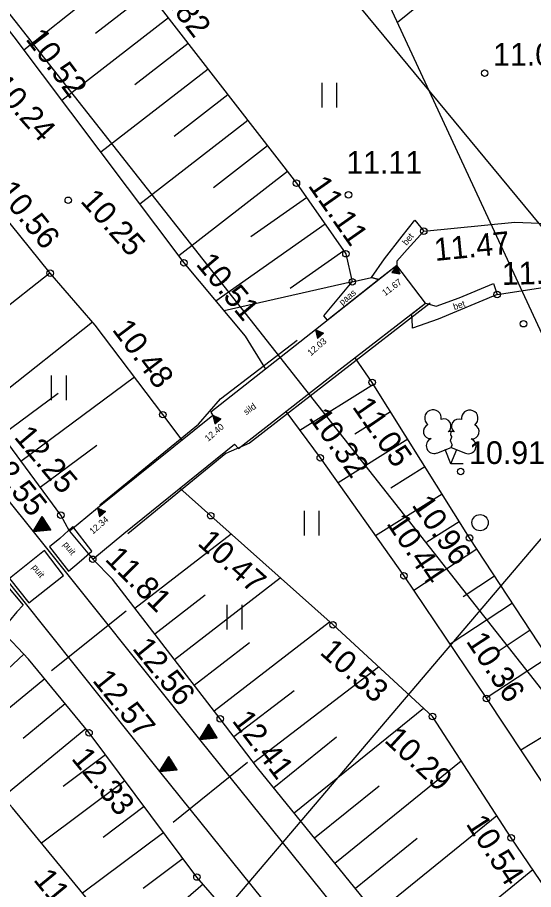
# Model space of a CAD drawing. Extents: x 554198 to 554371, y 6593448 to 6593563.
# Drawn here: x 554296.62 to 554312.55, y 6593507.8 to 6593534.71 of the extents above; entities that cross this region are included whole.
import ezdxf

# ---------------------------------------------------------------- set-up
doc = ezdxf.new("R2010")
doc.units = 0
for name, color, linetype in [('AED', 7, 'Continuous'), ('HALJASTUS', 7, 'Continuous'), ('KORGUS-EH2000', 7, 'Continuous'), ('PIIR', 7, 'Continuous'), ('POST', 7, 'Continuous'), ('PUU', 7, 'Continuous'), ('RAJATIS', 7, 'Continuous'), ('RAJATISEDET', 7, 'Continuous'), ('RDT', 7, 'Continuous'), ('RELJEEF', 7, 'Continuous'), ('SIOHULIIN', 7, 'Continuous'), ('TEE', 7, 'Continuous'), ('VTRASS', 7, 'Continuous')]:
    doc.layers.add(name, color=color, linetype=linetype)

msp = doc.modelspace()

# ---------------------------------------------------------------- linework, layer by layer
at = {"layer": 'AED'}
for points in [[(554309.359, 6593525.893), (554303.78, 6593521.577), (554303.057, 6593521.253), (554300.026, 6593518.783)], [(554299.165, 6593519.676), (554302.21, 6593522.165), (554302.89, 6593522.94), (554305.253, 6593524.758), (554305.253, 6593524.758)]]:
    msp.add_lwpolyline(points, dxfattribs=at)
at = {"layer": 'HALJASTUS'}
for p, q in [((554306.014, 6593532.693), (554306.014, 6593531.932)), ((554306.469, 6593532.693), (554306.469, 6593531.932)), ((554297.665, 6593523.668), (554297.665, 6593522.907)), ((554298.121, 6593523.668), (554298.121, 6593522.907)), ((554305.471, 6593519.49), (554305.471, 6593518.729)), ((554305.927, 6593519.49), (554305.927, 6593518.729)), ((554303.088, 6593516.59), (554303.088, 6593515.829)), ((554303.543, 6593516.59), (554303.543, 6593515.829))]:
    msp.add_line(p, q, dxfattribs=at)
at = {"layer": 'KORGUS-EH2000'}
for p, q in [((554297.103, 6593518.851), (554297.388, 6593519.316)), ((554297.349, 6593519.252), (554297.311, 6593518.868)), ((554297.379, 6593519.3), (554297.336, 6593518.871)), ((554297.403, 6593519.293), (554297.361, 6593518.873)), ((554297.425, 6593519.257), (554297.387, 6593518.875)), ((554297.647, 6593518.897), (554297.388, 6593519.316)), ((554297.199, 6593519.007), (554297.184, 6593518.858)), ((554297.229, 6593519.056), (554297.209, 6593518.86)), ((554297.259, 6593519.105), (554297.235, 6593518.862)), ((554297.289, 6593519.154), (554297.26, 6593518.864)), ((554297.319, 6593519.203), (554297.285, 6593518.866)), ((554297.446, 6593519.222), (554297.412, 6593518.877)), ((554297.468, 6593519.187), (554297.437, 6593518.879)), ((554297.489, 6593519.152), (554297.463, 6593518.881)), ((554297.511, 6593519.117), (554297.488, 6593518.883)), ((554297.533, 6593519.082), (554297.513, 6593518.885)), ((554297.554, 6593519.047), (554297.539, 6593518.888)), ((554297.576, 6593519.012), (554297.564, 6593518.89)), ((554297.103, 6593518.851), (554297.647, 6593518.897)), ((554297.109, 6593518.861), (554297.108, 6593518.851)), ((554297.139, 6593518.909), (554297.133, 6593518.854)), ((554297.169, 6593518.958), (554297.159, 6593518.856)), ((554297.598, 6593518.976), (554297.589, 6593518.892)), ((554297.619, 6593518.941), (554297.615, 6593518.894)), ((554297.641, 6593518.906), (554297.64, 6593518.896)), ((554302.239, 6593512.436), (554302.524, 6593512.901)), ((554302.485, 6593512.837), (554302.447, 6593512.453)), ((554302.515, 6593512.885), (554302.472, 6593512.456)), ((554302.539, 6593512.878), (554302.497, 6593512.458)), ((554302.561, 6593512.842), (554302.523, 6593512.46)), ((554302.783, 6593512.482), (554302.524, 6593512.901)), ((554302.582, 6593512.807), (554302.548, 6593512.462)), ((554302.305, 6593512.543), (554302.295, 6593512.441)), ((554302.335, 6593512.592), (554302.32, 6593512.443)), ((554302.365, 6593512.641), (554302.345, 6593512.445)), ((554302.395, 6593512.69), (554302.371, 6593512.447)), ((554302.425, 6593512.739), (554302.396, 6593512.449)), ((554302.455, 6593512.788), (554302.421, 6593512.451)), ((554302.604, 6593512.772), (554302.573, 6593512.464)), ((554302.625, 6593512.737), (554302.599, 6593512.466)), ((554302.647, 6593512.702), (554302.624, 6593512.468)), ((554302.669, 6593512.667), (554302.649, 6593512.47)), ((554302.69, 6593512.632), (554302.675, 6593512.473)), ((554302.712, 6593512.597), (554302.7, 6593512.475)), ((554302.734, 6593512.561), (554302.725, 6593512.477)), ((554302.755, 6593512.526), (554302.751, 6593512.479)), ((554302.239, 6593512.436), (554302.783, 6593512.482)), ((554302.245, 6593512.446), (554302.244, 6593512.436)), ((554302.275, 6593512.494), (554302.269, 6593512.439)), ((554302.777, 6593512.491), (554302.776, 6593512.481)), ((554301.007, 6593511.447), (554301.292, 6593511.912)), ((554301.193, 6593511.75), (554301.164, 6593511.46)), ((554301.223, 6593511.799), (554301.189, 6593511.462)), ((554301.253, 6593511.848), (554301.215, 6593511.464)), ((554301.283, 6593511.896), (554301.24, 6593511.467)), ((554301.307, 6593511.889), (554301.265, 6593511.469)), ((554301.329, 6593511.853), (554301.291, 6593511.471)), ((554301.551, 6593511.493), (554301.292, 6593511.912)), ((554301.35, 6593511.818), (554301.316, 6593511.473)), ((554301.372, 6593511.783), (554301.341, 6593511.475)), ((554301.393, 6593511.748), (554301.367, 6593511.477)), ((554301.415, 6593511.713), (554301.392, 6593511.479)), ((554301.007, 6593511.447), (554301.551, 6593511.493)), ((554301.013, 6593511.457), (554301.012, 6593511.447)), ((554301.043, 6593511.505), (554301.037, 6593511.45)), ((554301.073, 6593511.554), (554301.063, 6593511.452)), ((554301.103, 6593511.603), (554301.088, 6593511.454)), ((554301.133, 6593511.652), (554301.113, 6593511.456)), ((554301.163, 6593511.701), (554301.139, 6593511.458)), ((554301.437, 6593511.678), (554301.417, 6593511.481)), ((554301.458, 6593511.643), (554301.443, 6593511.484)), ((554301.48, 6593511.608), (554301.468, 6593511.486)), ((554301.502, 6593511.572), (554301.493, 6593511.488)), ((554301.523, 6593511.537), (554301.519, 6593511.49)), ((554301.545, 6593511.502), (554301.544, 6593511.492))]:
    msp.add_line(p, q, dxfattribs=at)
for centre in [(554311.04, 6593532.99), (554305.23, 6593529.6), (554306.84, 6593529.24), (554298.19, 6593529.07), (554309.16, 6593528.115), (554306.759, 6593527.42), (554301.76, 6593527.14), (554297.63, 6593526.82), (554306.956, 6593526.554), (554311.427, 6593526.164), (554312.24, 6593525.26), (554307.568, 6593523.452), (554301.107, 6593522.455), (554305.968, 6593521.122), (554310.3, 6593520.7), (554297.959, 6593519.355), (554302.586, 6593519.337), (554310.57, 6593518.65), (554298.943, 6593517.994), (554308.55, 6593517.48), (554306.36, 6593515.97), (554311.096, 6593513.696), (554302.88, 6593513.07), (554309.432, 6593513.141), (554298.83, 6593512.64), (554311.86, 6593509.4), (554302.161, 6593508.188)]:
    msp.add_circle(centre, 0.1, dxfattribs=at)
at = {"layer": 'PIIR'}
for p, q in [((554289.426, 6593543.649), (554309.59, 6593518.04)), ((554309.59, 6593518.04), (554321.626, 6593502.754))]:
    msp.add_line(p, q, dxfattribs=at)
at = {"layer": 'POST'}
msp.add_circle((554310.899, 6593519.124), 0.25, dxfattribs=at)
at = {"layer": 'PUU'}
for p, q in [((554309.561, 6593521.271), (554310.006, 6593521.446)), ((554310.006, 6593521.446), (554310.446, 6593521.266)), ((554310.001, 6593520.936), (554309.826, 6593521.376)), ((554310.001, 6593520.936), (554310.181, 6593521.376)), ((554310.381, 6593520.936), (554310.001, 6593520.936))]:
    msp.add_line(p, q, dxfattribs=at)
msp.add_lwpolyline([(554310.006, 6593521.941), (554309.986, 6593521.866), (554309.986, 6593521.846), (554309.996, 6593521.816), (554310.016, 6593521.781), (554310.021, 6593521.761), (554310.006, 6593521.726), (554309.981, 6593521.676), (554309.976, 6593521.651), (554309.981, 6593521.636), (554309.991, 6593521.606), (554310.026, 6593521.546), (554310.031, 6593521.526), (554310.026, 6593521.506), (554310.011, 6593521.471), (554310.006, 6593521.446)], dxfattribs=at)
for centre, radius, start, end in [((554309.444, 6593522.35), 0.256, 111.5027, 232.5173), ((554309.444, 6593522.35), 0.256, 350.4856, 111.5002), ((554310.58, 6593522.341), 0.256, 67.6168, 188.6314), ((554310.58, 6593522.341), 0.256, 306.5997, 67.6143), ((554309.779, 6593522.1), 0.224, 308.5041, 111.5725), ((554310.242, 6593522.095), 0.225, 67.7016, 230.5126), ((554309.37, 6593521.939), 0.224, 111.4304, 274.4987), ((554310.005, 6593521.703), 0.237, 66.7655, 111.5015), ((554310.647, 6593521.929), 0.224, 264.6183, 67.6866), ((554309.475, 6593521.494), 0.237, 111.5014, 291.5004), ((554310.536, 6593521.486), 0.237, 247.6166, 67.6155)]:
    msp.add_arc(centre, radius, start, end, dxfattribs=at)
at = {"layer": 'RAJATIS'}
for points in [[(554303.446, 6593521.406), (554306.637, 6593523.901), (554309.218, 6593525.899), (554308.331, 6593527.062), (554305.816, 6593525.073), (554302.594, 6593522.531), (554302.648, 6593522.432), (554299.091, 6593519.572), (554298.491, 6593519.075), (554298.228, 6593518.857), (554298.943, 6593517.994), (554299.902, 6593518.791), (554303.315, 6593521.546)], [(554296.378, 6593517.399), (554296.971, 6593516.654), (554298.04, 6593517.497), (554297.458, 6593518.268)], [(554295.41, 6593516.667), (554295.987, 6593517.134), (554296.216, 6593517.272), (554296.795, 6593516.578), (554296.603, 6593516.372), (554296.134, 6593515.797)]]:
    msp.add_lwpolyline(points, close=True, dxfattribs=at)
msp.add_lwpolyline([(554297.61, 6593518.38), (554298.199, 6593517.628), (554298.529, 6593517.903), (554298.914, 6593518.24), (554298.331, 6593519.007), (554297.925, 6593518.636), (554297.61, 6593518.38)], dxfattribs=at)
at = {"layer": 'RAJATISEDET'}
for p, q in [((554308.331, 6593527.062), (554308.175, 6593526.838)), ((554308.333, 6593527.057), (554308.33, 6593527.06)), ((554308.331, 6593527.062), (554308.419, 6593526.804)), ((554308.175, 6593526.838), (554308.419, 6593526.804)), ((554308.18, 6593526.838), (554308.177, 6593526.841)), ((554308.201, 6593526.835), (554308.184, 6593526.852)), ((554308.221, 6593526.832), (554308.191, 6593526.862)), ((554308.241, 6593526.829), (554308.198, 6593526.872)), ((554308.262, 6593526.826), (554308.206, 6593526.883)), ((554308.282, 6593526.823), (554308.213, 6593526.893)), ((554308.303, 6593526.82), (554308.22, 6593526.904)), ((554308.323, 6593526.817), (554308.228, 6593526.914)), ((554308.344, 6593526.814), (554308.235, 6593526.925)), ((554308.364, 6593526.811), (554308.242, 6593526.935)), ((554308.384, 6593526.808), (554308.249, 6593526.945)), ((554308.405, 6593526.806), (554308.257, 6593526.956)), ((554308.416, 6593526.812), (554308.264, 6593526.966)), ((554308.406, 6593526.84), (554308.271, 6593526.977)), ((554308.397, 6593526.867), (554308.279, 6593526.987)), ((554308.388, 6593526.894), (554308.286, 6593526.997)), ((554308.379, 6593526.921), (554308.293, 6593527.008)), ((554308.37, 6593526.948), (554308.3, 6593527.018)), ((554308.36, 6593526.975), (554308.308, 6593527.029)), ((554308.351, 6593527.002), (554308.315, 6593527.039)), ((554308.342, 6593527.03), (554308.322, 6593527.05)), ((554305.816, 6593525.073), (554306.068, 6593524.967)), ((554305.816, 6593525.073), (554305.88, 6593524.808)), ((554305.821, 6593525.071), (554305.817, 6593525.071)), ((554305.848, 6593525.06), (554305.82, 6593525.058)), ((554305.874, 6593525.049), (554305.823, 6593525.046)), ((554305.9, 6593525.037), (554305.825, 6593525.033)), ((554305.927, 6593525.026), (554305.828, 6593525.021)), ((554305.953, 6593525.015), (554305.831, 6593525.009)), ((554305.98, 6593525.004), (554305.834, 6593524.996)), ((554306.006, 6593524.993), (554305.837, 6593524.984)), ((554306.033, 6593524.982), (554305.84, 6593524.972)), ((554306.059, 6593524.971), (554305.843, 6593524.959)), ((554306.057, 6593524.958), (554305.846, 6593524.947)), ((554306.041, 6593524.945), (554305.849, 6593524.935)), ((554306.026, 6593524.932), (554305.852, 6593524.922)), ((554306.01, 6593524.918), (554305.855, 6593524.91)), ((554305.994, 6593524.905), (554305.858, 6593524.898)), ((554305.88, 6593524.808), (554306.068, 6593524.967)), ((554305.978, 6593524.891), (554305.861, 6593524.885)), ((554305.963, 6593524.878), (554305.864, 6593524.873)), ((554305.947, 6593524.865), (554305.867, 6593524.86)), ((554305.931, 6593524.851), (554305.87, 6593524.848)), ((554305.915, 6593524.838), (554305.873, 6593524.836)), ((554305.9, 6593524.825), (554305.876, 6593524.823)), ((554305.884, 6593524.811), (554305.879, 6593524.811)), ((554302.648, 6593522.432), (554302.9, 6593522.326)), ((554302.648, 6593522.432), (554302.712, 6593522.167)), ((554302.653, 6593522.43), (554302.649, 6593522.43)), ((554302.68, 6593522.419), (554302.652, 6593522.417)), ((554302.706, 6593522.408), (554302.655, 6593522.405)), ((554302.732, 6593522.396), (554302.657, 6593522.392)), ((554302.759, 6593522.385), (554302.66, 6593522.38)), ((554302.785, 6593522.374), (554302.663, 6593522.368)), ((554302.812, 6593522.363), (554302.666, 6593522.355)), ((554302.838, 6593522.352), (554302.669, 6593522.343)), ((554302.865, 6593522.341), (554302.672, 6593522.331)), ((554302.891, 6593522.33), (554302.675, 6593522.318)), ((554302.889, 6593522.317), (554302.678, 6593522.306)), ((554302.873, 6593522.304), (554302.681, 6593522.294)), ((554302.858, 6593522.291), (554302.684, 6593522.281)), ((554302.842, 6593522.277), (554302.687, 6593522.269)), ((554302.826, 6593522.264), (554302.69, 6593522.257)), ((554302.81, 6593522.25), (554302.693, 6593522.244)), ((554302.795, 6593522.237), (554302.696, 6593522.232)), ((554302.779, 6593522.224), (554302.699, 6593522.219)), ((554302.763, 6593522.21), (554302.702, 6593522.207)), ((554302.712, 6593522.167), (554302.9, 6593522.326)), ((554302.747, 6593522.197), (554302.705, 6593522.195)), ((554302.732, 6593522.184), (554302.708, 6593522.182)), ((554302.716, 6593522.17), (554302.711, 6593522.17)), ((554299.091, 6593519.572), (554299.343, 6593519.466)), ((554299.091, 6593519.572), (554299.155, 6593519.307)), ((554299.096, 6593519.57), (554299.092, 6593519.57)), ((554299.123, 6593519.559), (554299.095, 6593519.557)), ((554299.149, 6593519.548), (554299.098, 6593519.545)), ((554299.175, 6593519.536), (554299.1, 6593519.532)), ((554299.202, 6593519.525), (554299.103, 6593519.52)), ((554299.228, 6593519.514), (554299.106, 6593519.508)), ((554299.255, 6593519.503), (554299.109, 6593519.495)), ((554299.281, 6593519.492), (554299.112, 6593519.483)), ((554299.308, 6593519.481), (554299.115, 6593519.471)), ((554299.334, 6593519.47), (554299.118, 6593519.458)), ((554299.332, 6593519.457), (554299.121, 6593519.446)), ((554299.316, 6593519.444), (554299.124, 6593519.434)), ((554299.301, 6593519.431), (554299.127, 6593519.421)), ((554299.285, 6593519.417), (554299.13, 6593519.409)), ((554299.269, 6593519.404), (554299.133, 6593519.397)), ((554299.253, 6593519.39), (554299.136, 6593519.384)), ((554299.238, 6593519.377), (554299.139, 6593519.372)), ((554299.222, 6593519.364), (554299.142, 6593519.359)), ((554299.206, 6593519.35), (554299.145, 6593519.347)), ((554299.19, 6593519.337), (554299.148, 6593519.335)), ((554299.175, 6593519.324), (554299.151, 6593519.322)), ((554299.159, 6593519.31), (554299.154, 6593519.31)), ((554299.155, 6593519.307), (554299.343, 6593519.466))]:
    msp.add_line(p, q, dxfattribs=at)
at = {"layer": 'RDT'}
for p, q in [((554297.669, 6593514.56), (554299.972, 6593516.404)), ((554301.424, 6593509.877), (554303.721, 6593511.728))]:
    msp.add_line(p, q, dxfattribs=at)
for points in [[(554285.824, 6593532.905), (554287.956, 6593530.229), (554292.884, 6593524.093), (554297.103, 6593518.851), (554302.239, 6593512.436), (554306.663, 6593506.945), (554311.64, 6593500.773)], [(554284.588, 6593531.92), (554286.722, 6593529.242), (554291.653, 6593523.103), (554295.871, 6593517.862), (554301.007, 6593511.447), (554305.433, 6593505.953), (554310.41, 6593499.781)]]:
    msp.add_lwpolyline(points, dxfattribs=at)
at = {"layer": 'RELJEEF'}
for p, q in [((554300.05, 6593536.275), (554296.821, 6593533.697)), ((554300.668, 6593535.488), (554299.027, 6593534.217)), ((554301.28, 6593534.698), (554297.988, 6593532.147)), ((554301.893, 6593533.907), (554300.241, 6593532.628)), ((554302.505, 6593533.117), (554299.192, 6593530.55)), ((554303.117, 6593532.327), (554301.455, 6593531.039)), ((554303.73, 6593531.536), (554300.395, 6593528.952)), ((554304.342, 6593530.746), (554302.67, 6593529.449)), ((554304.955, 6593529.955), (554301.598, 6593527.354)), ((554305.546, 6593529.149), (554303.824, 6593527.941)), ((554306.121, 6593528.33), (554302.744, 6593525.962)), ((554306.695, 6593527.512), (554305.041, 6593526.352)), ((554294.276, 6593524.184), (554297.618, 6593526.835)), ((554306.956, 6593526.554), (554303.002, 6593525.654)), ((554295.517, 6593522.616), (554298.933, 6593525.32)), ((554296.724, 6593521.021), (554300.229, 6593523.618)), ((554307.607, 6593523.389), (554305.337, 6593521.97)), ((554296.129, 6593521.825), (554297.878, 6593523.121)), ((554308.137, 6593522.541), (554307.037, 6593521.853)), ((554308.667, 6593521.694), (554306.516, 6593520.349)), ((554297.32, 6593520.218), (554299.075, 6593521.519)), ((554309.197, 6593520.846), (554308.146, 6593520.189)), ((554309.728, 6593519.998), (554307.675, 6593518.714)), ((554310.258, 6593519.15), (554309.256, 6593518.523)), ((554300.246, 6593516.481), (554303.216, 6593518.775)), ((554310.796, 6593518.307), (554308.854, 6593517.028)), ((554301.468, 6593514.898), (554304.734, 6593517.421)), ((554311.346, 6593517.472), (554310.379, 6593516.835)), ((554300.857, 6593515.69), (554302.416, 6593516.894)), ((554311.896, 6593516.637), (554309.971, 6593515.369)), ((554302.69, 6593513.315), (554306.252, 6593516.066)), ((554312.446, 6593515.802), (554311.488, 6593515.17)), ((554302.079, 6593514.107), (554303.786, 6593515.425)), ((554296.818, 6593515.067), (554295.568, 6593513.897)), ((554312.996, 6593514.967), (554311.087, 6593513.709)), ((554303.906, 6593511.727), (554307.765, 6593514.676)), ((554297.463, 6593514.303), (554294.837, 6593512.146)), ((554303.299, 6593512.522), (554305.158, 6593513.943)), ((554298.098, 6593513.531), (554296.801, 6593512.465)), ((554305.161, 6593510.17), (554309.148, 6593513.403)), ((554314.076, 6593513.283), (554312.154, 6593512.099)), ((554298.733, 6593512.758), (554296.172, 6593510.654)), ((554304.531, 6593510.947), (554306.468, 6593512.517)), ((554299.337, 6593511.962), (554298.032, 6593510.985)), ((554306.421, 6593508.617), (554310.318, 6593511.776)), ((554299.936, 6593511.161), (554297.362, 6593509.235)), ((554305.791, 6593509.393), (554307.781, 6593511.007)), ((554300.536, 6593510.361), (554299.266, 6593509.411)), ((554307.68, 6593507.063), (554311.413, 6593510.089)), ((554301.135, 6593509.56), (554298.633, 6593507.688)), ((554307.05, 6593507.84), (554308.958, 6593509.386)), ((554301.734, 6593508.759), (554300.501, 6593507.837)), ((554308.94, 6593505.51), (554312.527, 6593508.418)), ((554302.349, 6593507.972), (554300.147, 6593506.056))]:
    msp.add_line(p, q, dxfattribs=at)
for points in [[(554296.626, 6593540.563), (554300.31, 6593535.95), (554305.23, 6593529.6), (554306.759, 6593527.42), (554306.956, 6593526.554)], [(554293.578, 6593537.902), (554296.51, 6593534.11), (554301.76, 6593527.14), (554303.649, 6593524.88), (554304.275, 6593523.857)], [(554301.7, 6593521.67), (554301.107, 6593522.455), (554299.02, 6593525.22), (554297.63, 6593526.82), (554294.593, 6593530.57), (554293.06, 6593532.23), (554290.734, 6593534.825), (554290.021, 6593535.62)], [(554298.228, 6593518.857), (554297.959, 6593519.355), (554295.91, 6593522.12), (554294.35, 6593524.09), (554291.583, 6593527.579), (554289.53, 6593530.22), (554286.714, 6593533.498)], [(554317.438, 6593507.521), (554315.31, 6593511.28), (554313.652, 6593513.971), (554310.57, 6593518.65), (554307.568, 6593523.452), (554307.04, 6593524.213)], [(554304.907, 6593522.548), (554305.968, 6593521.122), (554308.55, 6593517.48), (554311.096, 6593513.696), (554313.38, 6593510.25), (554316.014, 6593506.453)], [(554314.721, 6593505.189), (554311.86, 6593509.4), (554309.432, 6593513.141), (554306.36, 6593515.97), (554302.586, 6593519.337), (554301.632, 6593520.188)], [(554312.081, 6593501.733), (554310.829, 6593503.179), (554307.48, 6593507.31), (554304.034, 6593511.56), (554302.88, 6593513.07), (554299.553, 6593517.378), (554298.943, 6593517.994)], [(554309.146, 6593499.81), (554306.76, 6593502.86), (554304.63, 6593505.35), (554302.161, 6593508.188), (554298.83, 6593512.64), (554296.962, 6593514.913), (554296.134, 6593515.797)], [(554307.25, 6593498.822), (554304.78, 6593501.39), (554302.37, 6593503.94), (554299.35, 6593506.815), (554296.47, 6593510.32), (554294.416, 6593512.617), (554293.599, 6593513.53), (554293.482, 6593513.659)]]:
    msp.add_lwpolyline(points, dxfattribs=at)
at = {"layer": 'SIOHULIIN'}
for points in [[(554314.701, 6593520.885), (554304.707, 6593542.403)], [(554308.348, 6593534.564), (554317.867, 6593542.251), (554322.366, 6593542.251)], [(554314.701, 6593520.885), (554283.22, 6593483.889)]]:
    msp.add_lwpolyline(points, dxfattribs=at)
at = {"layer": 'TEE'}
msp.add_lwpolyline([(554307.774, 6593526.621), (554307.694, 6593526.645), (554307.543, 6593526.69), (554307.949, 6593527.265), (554308.492, 6593527.96), (554308.889, 6593528.455), (554309.16, 6593528.115), (554308.647, 6593527.549), (554308.334, 6593527.19), (554308.331, 6593527.062)], close=True, dxfattribs=at)
for points in [[(554309.16, 6593528.115), (554311.97, 6593528.39), (554317.98, 6593528.15), (554322.11, 6593527.91), (554324.87, 6593527.83)], [(554306.186, 6593525.366), (554306.081, 6593525.506), (554306.956, 6593526.554), (554307.543, 6593526.69), (554307.694, 6593526.645), (554307.774, 6593526.621), (554306.186, 6593525.366)], [(554310.25, 6593526.056), (554311.318, 6593526.499), (554311.427, 6593526.164), (554309.604, 6593525.403), (554308.814, 6593525.12), (554308.798, 6593525.421), (554308.78, 6593525.56), (554309.218, 6593525.899), (554309.548, 6593525.807), (554310.25, 6593526.056)], [(554311.427, 6593526.164), (554313.1, 6593526.42), (554316.52, 6593526.1), (554319.19, 6593525.42), (554320.94, 6593524.69), (554321.97, 6593524.35), (554324.187, 6593524.57), (554324.75, 6593524.63)]]:
    msp.add_lwpolyline(points, dxfattribs=at)
at = {"layer": 'VTRASS'}
msp.add_lwpolyline([(554301.662, 6593541.71), (554320.208, 6593519.297), (554320.351, 6593519.114), (554320.451, 6593518.973), (554327.895, 6593509.98)], dxfattribs=at)

# ---------------------------------------------------------------- texts
at = {"layer": 'KORGUS-EH2000'}
for s, rotation, p in [(' 10.82 ', 307.7686, (554300.494, 6593536.093)), (' 10.52 ', 306.9881, (554296.696, 6593534.25)), (' 10.24 ', 311.8711, (554295.604, 6593532.766)), (' 11.11 ', 305.0449, (554305.421, 6593529.734)), (' 10.56 ', 309.0029, (554295.803, 6593529.527)), (' 10.25 ', 311.8711, (554298.364, 6593529.226)), (' 11.47 ', 5.5894, (554309.253, 6593527.17)), (' 10.51 ', 309.8903, (554301.939, 6593527.29)), (' 11.43 ', 1.3163, (554311.317, 6593526.45)), (' 10.48 ', 307.0452, (554299.367, 6593525.282)), (' 11.05 ', 304.7538, (554306.787, 6593522.91)), (' 10.32 ', 305.3348, (554305.44, 6593522.568)), (' 12.25 ', 310.0098, (554296.323, 6593521.954)), (' 12.55 ', 308.6816, (554295.419, 6593521.29)), (' 10.96 ', 304.7538, (554308.623, 6593519.88)), (' 10.44 ', 303.934, (554307.848, 6593519.315)), (' 10.47 ', 318.266, (554301.954, 6593518.628)), (' 11.81 ', 314.7196, (554299.109, 6593518.158)), (' 12.56 ', 308.8578, (554299.981, 6593515.438)), (' 10.36 ', 303.5363, (554310.304, 6593515.682)), (' 10.53 ', 318.262, (554305.728, 6593515.261)), (' 12.57 ', 308.8551, (554298.749, 6593514.449)), (' 12.41 ', 307.3885, (554303.065, 6593513.212)), (' 10.29 ', 317.3581, (554307.721, 6593512.555)), (' 12.33 ', 309.4141, (554298.096, 6593512.037)), (' 10.54 ', 302.9846, (554310.303, 6593510.048)), (' 11.42 ', 309.4094, (554296.926, 6593508.299))]:
    msp.add_text(s, height=0.7, rotation=rotation, dxfattribs=at).set_placement(p)
for s, p in [(' 11.05 ', (554311.04, 6593533.223)), (' 11.11 ', (554306.509, 6593529.886)), (' 10.91 ', (554310.3, 6593520.933))]:
    msp.add_text(s, height=0.7, dxfattribs=at).set_placement(p)
at = {"layer": 'RAJATIS'}
for s, rotation, p in [('sild', 35.5555, (554303.683, 6593522.434)), ('puit', 307.9626, (554298.016, 6593518.444)), ('puit', 307.9626, (554297.055, 6593517.743))]:
    msp.add_text(s, height=0.2, rotation=rotation, dxfattribs=at).set_placement(p)
at = {"layer": 'RAJATISEDET'}
for s, rotation, p in [('11.67', 36.6056, (554307.967, 6593526.105)), ('12.03', 40.8947, (554305.676, 6593524.254)), ('12.40', 40.8947, (554302.508, 6593521.613)), ('12.34', 40.8947, (554298.947, 6593518.75))]:
    msp.add_text(s, height=0.2, rotation=rotation, dxfattribs=at).set_placement(p)
at = {"layer": 'TEE'}
for s, rotation, p in [('bet', 50.8965, (554308.631, 6593527.663)), ('paas', 40.003, (554306.648, 6593525.814)), ('bet', 18.7682, (554310.106, 6593525.68))]:
    msp.add_text(s, height=0.2, rotation=rotation, dxfattribs=at).set_placement(p)

doc.saveas('drawing.dxf')
